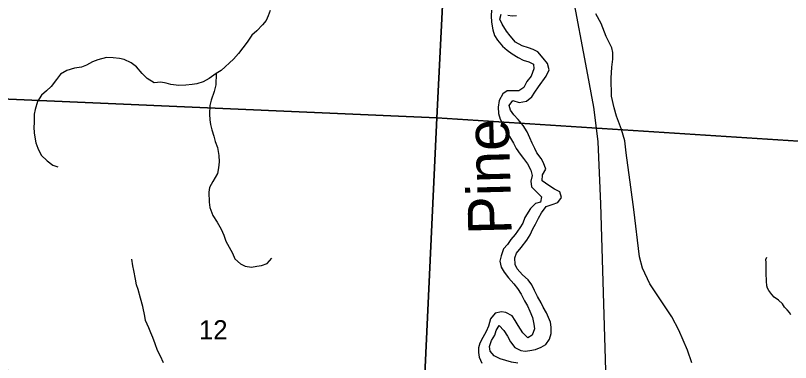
# Model space of a CAD drawing. Extents: x 0 to 34, y 0 to 22.
# Drawn here: x 3.511 to 5.204, y 18.059 to 18.818 of the extents above; entities that cross this region are included whole.
import ezdxf

# ---------------------------------------------------------------- set-up
doc = ezdxf.new("R2010")
doc.units = 0
for name, color, linetype in [('GM_X_Minor_River', 7, 'Continuous'), ('GM_X_Minor_River_Text', 7, 'Continuous'), ('GM_X_Rail_Line', 7, 'Continuous'), ('GM_X_Section', 7, 'Continuous'), ('GM_X_Section_Text', 7, 'Continuous'), ('GM_X_State_Route', 7, 'Continuous')]:
    doc.layers.add(name, color=color, linetype=linetype)

msp = doc.modelspace()

# ---------------------------------------------------------------- linework, layer by layer
at = {"layer": 'GM_X_Minor_River'}
for points in [[(4.0669, 18.8288), (4.0624, 18.8174), (4.058, 18.8075), (4.0501, 18.7979), (4.0381, 18.7845), (4.0268, 18.7749), (4.0171, 18.76), (3.9976, 18.7347), (3.9867, 18.7225), (3.9596, 18.6979), (3.9487, 18.6914), (3.9336, 18.6806), (3.9204, 18.6729), (3.9068, 18.6686), (3.8969, 18.6673), (3.8825, 18.6661), (3.8673, 18.6648), (3.8499, 18.6669), (3.84, 18.6702), (3.8282, 18.672), (3.8134, 18.6711), (3.7985, 18.6805), (3.7874, 18.6914), (3.7751, 18.706), (3.7632, 18.7147), (3.7483, 18.7221), (3.7381, 18.7239), (3.7244, 18.7257), (3.7092, 18.7263), (3.6903, 18.7208), (3.6786, 18.7165), (3.6657, 18.7096), (3.6548, 18.7049), (3.6396, 18.7028), (3.623, 18.6978), (3.609, 18.6896), (3.6, 18.6778), (3.5884, 18.6625), (3.5782, 18.6537), (3.5677, 18.6441), (3.5591, 18.6303), (3.554, 18.6124), (3.5518, 18.6022), (3.5512, 18.5836), (3.5509, 18.5737), (3.5518, 18.5615), (3.553, 18.5521), (3.5555, 18.5396), (3.5594, 18.5282), (3.5671, 18.5127), (3.5801, 18.5003), (3.5924, 18.4909), (3.603, 18.4869)], [(4.5505, 18.8298), (4.5497, 18.8173), (4.5501, 18.8036), (4.5531, 18.7869), (4.5569, 18.7747), (4.5634, 18.7644), (4.5748, 18.7511), (4.5846, 18.7424), (4.5957, 18.734), (4.609, 18.7264), (4.6196, 18.7207), (4.6318, 18.7165), (4.642, 18.7119), (4.6431, 18.7017), (4.6371, 18.6857), (4.6279, 18.6735), (4.6211, 18.6606), (4.6104, 18.6534), (4.585, 18.6534), (4.5755, 18.6466), (4.5671, 18.6322), (4.5648, 18.6177), (4.5659, 18.604), (4.5697, 18.5915), (4.5769, 18.5782), (4.5849, 18.5626), (4.5917, 18.55), (4.5982, 18.5386), (4.6046, 18.5276), (4.6134, 18.5147), (4.6202, 18.5052), (4.6293, 18.4934), (4.6362, 18.4801), (4.6392, 18.4683), (4.6365, 18.4561), (4.6376, 18.4436), (4.6471, 18.4341), (4.6597, 18.4219), (4.6574, 18.4097), (4.6464, 18.4071), (4.6357, 18.3964), (4.6235, 18.3767), (4.619, 18.3641), (4.6125, 18.3539), (4.6022, 18.3391), (4.5927, 18.3284), (4.5851, 18.3174), (4.5767, 18.3075), (4.5718, 18.2927), (4.5687, 18.2809), (4.5714, 18.2676), (4.5782, 18.257), (4.5873, 18.2444), (4.5991, 18.2315), (4.6075, 18.2209), (4.6151, 18.2087), (4.6223, 18.1939), (4.6291, 18.1832), (4.634, 18.1714), (4.6401, 18.1577), (4.6428, 18.1433), (4.6443, 18.1326), (4.6393, 18.1193), (4.6298, 18.1133), (4.6192, 18.1239), (4.6089, 18.1399), (4.6021, 18.1513), (4.5953, 18.1612), (4.582, 18.1688), (4.5725, 18.17), (4.5588, 18.1669), (4.5481, 18.1548), (4.5436, 18.1384), (4.539, 18.127), (4.5318, 18.1141), (4.5253, 18.1016), (4.5219, 18.0913), (4.5219, 18.081), (4.5238, 18.0712), (4.5294, 18.0579)], [(4.6465, 18.0877), (4.659, 18.093), (4.6689, 18.0983), (4.6769, 18.1101), (4.6811, 18.123), (4.6811, 18.1367), (4.6792, 18.1473), (4.6705, 18.1682), (4.6633, 18.1804), (4.6591, 18.1899), (4.6507, 18.2036), (4.6447, 18.2165), (4.6382, 18.2291), (4.6302, 18.2401), (4.6185, 18.2508), (4.6063, 18.2641), (4.6025, 18.2736), (4.6014, 18.2884), (4.6052, 18.2983), (4.6155, 18.3104), (4.6276, 18.3268), (4.6349, 18.3382), (4.6406, 18.3515), (4.6463, 18.3621), (4.6528, 18.375), (4.66, 18.3864), (4.6699, 18.4001), (4.6832, 18.405), (4.695, 18.4092), (4.703, 18.4202), (4.6995, 18.4324), (4.6878, 18.4385), (4.676, 18.4465), (4.6612, 18.4564), (4.6619, 18.4693), (4.6688, 18.4818), (4.6642, 18.4959), (4.6589, 18.5054), (4.6498, 18.5179), (4.6449, 18.5275), (4.6396, 18.5392), (4.6339, 18.5506), (4.6282, 18.5636), (4.6198, 18.5773), (4.6084, 18.5906), (4.5989, 18.6012), (4.5921, 18.6111), (4.5894, 18.621), (4.5974, 18.632), (4.6107, 18.6275), (4.6267, 18.6305), (4.6389, 18.64), (4.645, 18.6506), (4.6529, 18.6624), (4.6701, 18.6852), (4.6762, 18.6996), (4.6727, 18.7129), (4.6633, 18.7247), (4.6515, 18.7384), (4.6416, 18.7434), (4.6313, 18.7472), (4.6177, 18.7517), (4.6032, 18.7601), (4.5911, 18.7738), (4.5835, 18.7841), (4.574, 18.7989), (4.5687, 18.8099), (4.5717, 18.8213)], [(4.5858, 18.8187), (4.5957, 18.8171), (4.6052, 18.8183)], [(3.9487, 18.6914), (3.9482, 18.6663), (3.9445, 18.6522), (3.9379, 18.6332), (3.9349, 18.6214), (3.9348, 18.6024), (3.9353, 18.5903), (3.9369, 18.58), (3.9393, 18.5679), (3.9436, 18.5539), (3.9467, 18.5429), (3.9522, 18.5293), (3.955, 18.5119), (3.9555, 18.4978), (3.9538, 18.4849), (3.9516, 18.4727), (3.9415, 18.4552), (3.9344, 18.4418), (3.933, 18.4316), (3.9336, 18.4096), (3.9349, 18.3982), (3.9415, 18.3808), (3.9511, 18.3664), (3.96, 18.3506), (3.9658, 18.3374), (3.9705, 18.3249), (3.9775, 18.3113), (3.9845, 18.2981), (3.9899, 18.2863), (4.0025, 18.2751), (4.0124, 18.2702), (4.0265, 18.2681), (4.0379, 18.2701), (4.0481, 18.2717), (4.0606, 18.2756), (4.0707, 18.2875)], [(3.8339, 18.0582), (3.8273, 18.0733), (3.8207, 18.0858), (3.8156, 18.1002), (3.8105, 18.1142), (3.8066, 18.1244), (3.802, 18.135), (3.795, 18.1509), (3.793, 18.1603), (3.7886, 18.1819), (3.7835, 18.1997), (3.7788, 18.2186), (3.7749, 18.2289), (3.7725, 18.2414), (3.7692, 18.2607), (3.7672, 18.2705), (3.7648, 18.2853)], [(5.2043, 18.1635), (5.2013, 18.1689), (5.1961, 18.1743), (5.1908, 18.18), (5.186, 18.1877), (5.1777, 18.1954), (5.1679, 18.2023), (5.1631, 18.2077), (5.1563, 18.2169), (5.153, 18.2219), (5.1519, 18.2269), (5.1513, 18.2368), (5.151, 18.2432), (5.1506, 18.2485), (5.1507, 18.2546), (5.1504, 18.2603), (5.1506, 18.2782), (5.1495, 18.2843), (5.1522, 18.2896)], [(4.6081, 18.0577), (4.594, 18.0603), (4.5815, 18.0634), (4.5697, 18.0676), (4.5564, 18.0737), (4.5473, 18.0843), (4.5461, 18.0942), (4.5503, 18.1071), (4.5576, 18.1193), (4.561, 18.1296), (4.5671, 18.1402), (4.5773, 18.1295), (4.5853, 18.1166), (4.5921, 18.1044), (4.6013, 18.0919), (4.6142, 18.0854), (4.624, 18.0843), (4.6343, 18.0858), (4.6465, 18.0877)]]:
    msp.add_lwpolyline(points, dxfattribs=at)
at = {"layer": 'GM_X_Rail_Line'}
msp.add_lwpolyline([(5.3195, 17.2344), (5.0671, 17.4139), (5.0106, 17.4538), (4.9679, 17.4828), (4.9471, 17.4992), (4.9206, 17.5297), (4.9053, 17.5563), (4.886, 17.6022), (4.8152, 17.8074), (4.808, 17.8412), (4.8048, 17.8814), (4.8031, 17.945), (4.7895, 18.4061), (4.7838, 18.542), (4.7798, 18.5718), (4.7742, 18.6177), (4.7589, 18.6998), (4.7275, 18.8672)], dxfattribs=at)
at = {"layer": 'GM_X_Section'}
for points in [[(3.4977, 19.6708), (4.4823, 19.6076), (4.4314, 18.5943), (3.4282, 18.6383)], [(4.4823, 19.6076), (5.5089, 19.5445), (5.4469, 18.529), (4.4314, 18.5943)], [(3.4282, 18.6383), (4.4314, 18.5943), (4.383, 17.5655), (3.6608, 17.6237), (3.615, 17.7371), (3.4191, 18.2301), (3.4042, 18.2698)], [(4.4314, 18.5943), (5.4469, 18.529), (5.3838, 17.5009), (4.383, 17.5655)]]:
    msp.add_lwpolyline(points, close=True, dxfattribs=at)
at = {"layer": 'GM_X_State_Route'}
msp.add_lwpolyline([(4.988, 18.0586), (4.9788, 18.0861), (4.9594, 18.1302), (4.9446, 18.1589), (4.8966, 18.2313), (4.8801, 18.2659), (4.8739, 18.2901), (4.8616, 18.394), (4.855, 18.4429), (4.8446, 18.5179), (4.8418, 18.544), (4.8347, 18.5691), (4.8233, 18.5981), (4.8181, 18.6161), (4.8128, 18.6417), (4.8117, 18.681), (4.8133, 18.7049), (4.8152, 18.7225), (4.8157, 18.7291), (4.8152, 18.7375), (4.8131, 18.7471), (4.8012, 18.7723), (4.7898, 18.8008), (4.7787, 18.8214)], dxfattribs=at)

# ---------------------------------------------------------------- texts
at = {"layer": 'GM_X_Minor_River_Text'}
msp.add_text('Pine', height=0.09469, rotation=91.493, dxfattribs=at).set_placement((4.5946, 18.34))
at = {"layer": 'GM_X_Section_Text'}
msp.add_text('12', height=0.04186, rotation=0, dxfattribs=at).set_placement((3.9116, 18.1099))

doc.saveas('drawing.dxf')
